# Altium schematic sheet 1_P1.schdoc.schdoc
size 309 x 223 mm; Symbol: Sheet-Symbol_A4; Device: Sheet-Symbol_A4; Company: EasyEDA.com; Drawed: EasyEDA Pro; Reviewed: EasyEDA Pro; Version: V0.1; Page Size: A4; @Project Name: CN3791; @Page Count: 1; @Update Date: 2023-11-26; @Create Date: 2023-11-17; @Schematic Name: Schematic1; Part Number: JLCPCB-002; @Page No: 1; @Page Name: P1
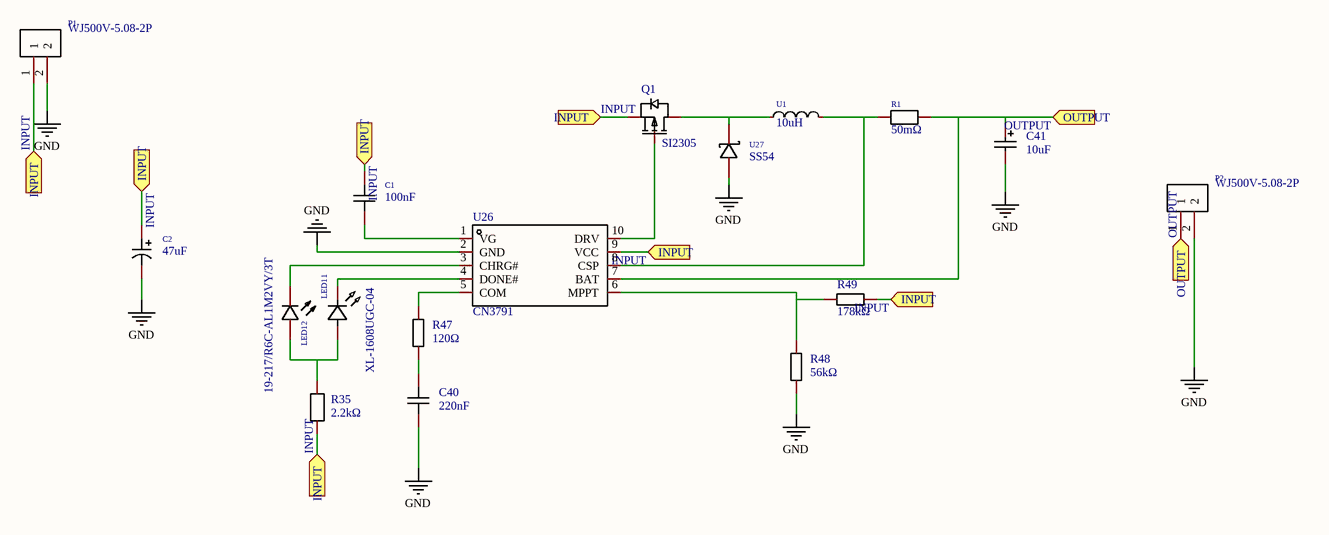
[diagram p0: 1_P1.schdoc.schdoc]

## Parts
C1  100nF  [C0402]
C2  47uF  [CAP-SMD_BD6.3-L6.6-W6.6-LS7.6-FD]
C40  220nF  [C0402]
C41  10uF  [CAP-SMD_L3.2-W1.6-RD]
LED11  XL-1608UGC-04  [LED0603-RD_GREEN]
LED12  19-217/R6C-AL1M2VY/3T  [LED0603-RD]
P1  WJ500V-5.08-2P  [CONN-TH_2P-P5.00_WJ500V-5.08-2P]
P2  WJ500V-5.08-2P  [CONN-TH_2P-P5.00_WJ500V-5.08-2P]
Q1  SI2305  [SOT-23-3_L2.9-W1.3-P1.90-LS2.4-BR]
R1  50mΩ  [R1206]
R35  2.2kΩ  [R2010]
R47  120Ω  [R0402]
R48  56kΩ  [R0402]
R49  178kΩ  [R0402]
U1  10uH  [IND-SMD_L7.2-W6.6_GPSR07X0]
U26  CN3791  [SSOP-10_L4.9-W3.9-P1.00-LS6.0-BL]
U27  SS54  [SMC_L6.9-W5.9-LS7.9-RD]

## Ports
INPUT (in), OUTPUT (in)

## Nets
GND: C2.2 C40.2 C41.2 P1.2 P2.2 R48.1 U26.2(GND) U27.2(A)
INPUT: C1.2 C2.1 P1.1 Q1.2(S) R35.2 R49.2 U26.9(VCC) ; port INPUT
OUTPUT: C41.1 P2.1 R1.2 U26.7(BAT) ; port OUTPUT
NetC1_1: C1.1 U26.1(VG)
NetC40_1: C40.1 R47.1
NetLED11_1: LED11.1(K) U26.4(DONE#)
NetLED11_2: LED11.2(A) LED12.2(A) R35.1
NetLED12_1: LED12.1(C) U26.3(CHRG#)
NetQ1_1: Q1.1(G) U26.10(DRV)
NetQ1_3: Q1.3(D) U1.1 U27.1(K)
NetR1_1: R1.1 U1.2 U26.8(CSP)
NetR47_2: R47.2 U26.5(COM)
NetR48_2: R48.2 R49.1 U26.6(MPPT)

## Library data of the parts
C1 = CT41G-0402-2X1-16V-0.1μF-K(N): Manufacturer: TORCH(火炬); Add into BOM: yes; Tolerance: ±10%; Description: Capacitance: Tolerance:±10% Tolerance:±10% Voltage Rated: Temperature Coefficient:
C2 = RVT47UF50V67RV0029: Manufacturer: KNSCHA(科尼盛); Add into BOM: yes; Tolerance: ±20%; Ripple Current: 66mA@120Hz; Lifetime @ Temp: 2000hrs@105℃; Description: Capacitance: Tolerance:±20% Tolerance:±20% Rated Voltage: Ripple Current:66mA@120Hz Equivalent Series Resistance(ESR):- φD: L: Lifetime @ Temp:2000hrs@105℃ Operating Temperature:-55℃~+105℃ Operating Temperature:-55℃~+105℃
C40 = 0402B224K160NT: Manufacturer: FH(风华); Add into BOM: yes; Tolerance: ±10%; Description: Capacitance: Tolerance:±10% Tolerance:±10% Voltage Rated: Temperature Coefficient:
C41 = CA45-A-16V-10uF-K: Manufacturer: CEC(振华新云); Add into BOM: yes; Tolerance: ±10%; Equivalent Series Resistance(ESR): 10Ω@100kHz; Description: Capacitance: Tolerance:±10% Tolerance:±10% Rated Voltage: Equivalent Series Resistance(ESR):10Ω@100kHz Operating Temperature:-55℃~+125℃ Operating Temperature:-55℃~+125℃
LED11 = XL-1608UGC-04: Manufacturer: XINGLIGHT(成兴光); Add into BOM: yes; Emitted Color: Emerald; Lens Color: Colorless transparence; Dominant Wavelength: 516nm~525nm; Peak Wavelength: 534nm; Forward Current: 25mA; Power Dissipation: 80mW; Viewing Angle: 120°; Mounting Sytle: Positive post; Description: Emitted Color:Emerald Lens Color:Colorless transparence Dominant Wavelength:516nm~525nm Dominant Wavelength:516nm~525nm Peak Wavelength:534nm Color Temperature:- Color Temperature:- Forward Current:25mA Power Dissipation:80mW Viewing Angle:120° Mounting S
LED12 = 19-217/R6C-AL1M2VY/3T: Manufacturer: EVERLIGHT(亿光); Add into BOM: yes; Emitted Color: 红灯; Lens Color: Colorless transparence; Dominant Wavelength: 617.5nm~633.5nm; Peak Wavelength: 632nm; Forward Current: 5mA; Power Dissipation: 60mW; Viewing Angle: 120°; Description: Emitted Color:红灯 Diode Configuration:- Lens Color:Colorless transparence Dominant Wavelength:617.5nm~633.5nm Dominant Wavelength:617.5nm~633.5nm Peak Wavelength:632nm Color Temperature:- Color Temperature:- Forward Current:5mA Power Dissipation:60mW Viewi
P1 P2 = WJ500V-5.08-2P: Manufacturer: KANGNEX(康奈克斯电气); Symbol: WJ500V-5.08-2P-14-00A; Add into BOM: yes; Structure: 1x2P; Pitch: 5.08mm; Current Rating (Max): 18A; Voltage Rating (Max): 250V; Wire Gauge - AWG: 14~30; Wire Gauge - mm2: 2.5; Number of PINs Per Row: 2; Description: Structure:1x2P Pitch:5.08mm Color:Green Mounting Style:Straight Current Rating (Max):18A Voltage Rating (Max):250V Number of Pins:2P Number of Rows:1 Wire Gauge - AWG:14~30 Wire Gauge - AWG:14~30 Wire Gauge - mm2:2.5 Wire Gauge - mm2:2.5 Number of PINs Pe
Q1 = SI2305_C2909911: Manufacturer: YONGYUTAI(永裕泰); Add into BOM: yes; Power Dissipation (Pd): 1200mW; Drain Source On Resistance (RDS(on)@Vgs,Id): 55mΩ@4.5V,3.9A; Gate Threshold Voltage (Vgs(th)@Id): 1.5V@250uA; Description: Type: Drain Source Voltage (Vdss): Continuous Drain Current (Id): Power Dissipation (Pd):1200mW Drain Source On Resistance (RDS(on)@Vgs,Id):55mΩ@4.5V,3.9A Gate Threshold Voltage (Vgs(th)@Id):1.5V@250uA Operating Temperature:+150℃@(Tj) Operating Temperatur
R1 = FRL1206JR050TS: Manufacturer: FOJAN(富捷); Add into BOM: yes; Tolerance: ±5%; Power(Watts): 250mW; Temperature Coefficient: ±1200ppm/℃; Description: Type:Thick Film Resistors Resistance:50mΩ Tolerance:±5% Tolerance:±5% Power(Watts):250mW Temperature Coefficient:±1200ppm/℃ Temperature Coefficient:±1200ppm/℃ Overload Voltage (Max):- Operating Temperature Range:-55℃~+155℃ Operating Temperature Range:-55℃
R35 = 201007J0222T4E: Manufacturer: UNI-ROYAL(厚声); Add into BOM: yes; Tolerance: ±5%; Temperature Coefficient: ±100ppm/℃; Description: Type:Thick Film Resistors Resistance: Tolerance:±5% Tolerance:±5% Power(Watts): Temperature Coefficient:±100ppm/℃ Temperature Coefficient:±100ppm/℃ Overload Voltage (Max): Operating Temperature Range:-55℃~+155℃ Operating Temperature Range:-55℃~+155℃
R47 = RC0402FR-07120RL: Manufacturer: YAGEO(国巨); Add into BOM: yes; Tolerance: ±1%; Temperature Coefficient: ±100ppm/℃; Description: Type:Thick Film Resistors Resistance: Tolerance:±1% Tolerance:±1% Power(Watts): Temperature Coefficient:±100ppm/℃ Temperature Coefficient:±100ppm/℃ Overload Voltage (Max): Operating Temperature Range:-55℃~+155℃ Operating Temperature Range:-55℃~+155℃
R48 = RC0402FR-0756KL: Manufacturer: YAGEO(国巨); Add into BOM: yes; Tolerance: ±1%; Temperature Coefficient: ±100ppm/℃; Description: Type:Thick Film Resistors Resistance: Tolerance:±1% Tolerance:±1% Power(Watts): Temperature Coefficient:±100ppm/℃ Temperature Coefficient:±100ppm/℃ Overload Voltage (Max): Operating Temperature Range:-55℃~+155℃ Operating Temperature Range:-55℃~+155℃
R49 = RM04FTN1783: Manufacturer: 大毅科技; Add into BOM: yes; Tolerance: ±1%; Temperature Coefficient: ±100ppm/℃; Description: Type:Thick Film Resistors Resistance: Tolerance:±1% Tolerance:±1% Power(Watts): Temperature Coefficient:±100ppm/℃ Temperature Coefficient:±100ppm/℃ Overload Voltage (Max): Operating Temperature Range:-55℃~+155℃ Operating Temperature Range:-55℃~+155℃
U1 = CYA0630-10UH: Manufacturer: SHOU HAN(首韩); Add into BOM: yes; Tolerance: ±20%; Description: Inductance: Tolerance:±20% Tolerance:±20% Rated Current: DC Resistance (DCR):
U26 = CN3791: Manufacturer: CONSONANCE(上海如韵); Add into BOM: yes
U27 = SS54_C5307984: Manufacturer: 晶扬电子; Add into BOM: yes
